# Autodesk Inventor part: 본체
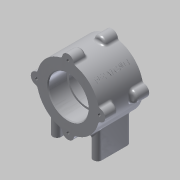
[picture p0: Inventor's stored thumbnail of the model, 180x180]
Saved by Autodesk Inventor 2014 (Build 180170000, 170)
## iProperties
Created: 2015-03
Part Number: 본체
Material: 알루미늄 6061
Document SubType Name: Modeling
Designer: MYHOME
Density: 2.71 g/cm^3
Appearance: 알루미늄 - 평지
Mass: 450.776 g
Surface Area: 332.745 cm^2
Volume: 166.338 cm^3
Author: MYHOME
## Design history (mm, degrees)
sketch "스케치2"
  geometry: C1 r 37 at (0, 0); 1 further point
  constraints: 1 centre point, 1 coincident
  dimensions: "d0" = 74 diameter of C1
extrude "돌출1" new body sketch "스케치2" distance "d1" = 26; taper "d2" = 0 deg
sketch "스케치3"
  geometry: C1 r 7 at (0, 37); C2 r 7 at (-37, 0); C3 r 7 at (37, 0); C4 r 7 at (0, -37); A1 r 37 centre (0, 0) between (0, 37) and (-37, 0) reference
  constraints: 4 centre point, 4 point on circle, 2 horizontal alignment, 2 vertical alignment
  dimensions: "d3" = 7 radius of C1; "d4" = 7 radius of C2; "d5" = 7 radius of C3; "d6" = 7 radius of C4
extrude "돌출2" join sketch "스케치3" distance "d7" = 15; taper "d8" = 0 deg
sketch "스케치4"
  geometry: A1 r 7 centre (37, 0) between (36.338, -6.969) and (36.338, 6.969) reference; A2 r 7 centre (0, 37) between (6.969, 36.338) and (-6.969, 36.338) reference; A3 r 7 centre (-37, 0) between (-36.338, 6.969) and (-36.338, -6.969) reference; A4 r 7 centre (0, -37) between (-6.969, -36.338) and (6.969, -36.338) reference; 4 further points
  constraints: 4 coincident
hole "구멍1" sketch "스케치4" at (0, 37), (-37, 0), (0, -37), (37, 0) diameter "d9" = 3.242; stored, may be unused: countersink angle "d13" = 90 deg, drill point angle "d15" = 118 deg; dims "d10" = 8, "d11" = 4, "d12" = 2, "d14" = 11
fillet "모깎기1" dims "d16" = 3
fillet "모깎기2" dims "d17" = 3
fillet "모깎기3" dims "d18" = 3
hole "구멍2" diameter "d21" = 42; stored, may be unused: countersink angle "d25" = 90 deg, drill point angle "d27" = 0 deg; dims "d19" = 10, "d20" = 10, "d22" = 8, "d23" = 47, "d24" = 22, "d26" = 26
chamfer "모따기1" distance "d28" = 1; stored, may be unused: second distance "d29" = 2, angle "d30" = 45 deg
fillet "모깎기4" dims "d31" = 0.3
node "작업 평면1"
sketch "스케치6"
  geometry: L1 (-24, 15)-(-24, -15); L2 (-29, 15)-(-29, -15); L3 (-19, -15)-(-19, 15); L4 (24, 15)-(24, -15); L5 (29, 15)-(29, -15); L6 (19, -15)-(19, 15); L7 (0, 0)-(0, 20); A1 r 5 centre (-24, 15) between (-19, 15) and (-29, 15); A2 r 5 centre (-24, -15) between (-29, -15) and (-19, -15); A3 r 5 centre (24, 15) between (29, 15) and (19, 15); A4 r 5 centre (24, -15) between (19, -15) and (29, -15); 2 further points
  constraints: 18 end point, 8 point on circle, 8 tangent, 4 centre point, 4 parallel, 2 horizontal alignment, 2 midpoint, 1 symmetric about line, 1 vertical
  dimensions: "d33" = 40 dimension on A3 A4; "d34" = 40 dimension on A1 A2; "d36" = 5 radius of A1; "d37" = 48 distance of L4.end L1.end; "d38" = 10 distance between parallel lines of L5 L6; "d39" = 20 distance of L7.start L7.end
extrude "돌출3" join sketch "스케치6" stored distance "d40" = 15; taper "d41" = 0 deg
sketch "스케치7"
  geometry: L1 (29, 15)-(29, -15) reference; L2 (19, -15)-(19, 15) reference; A1 r 5 centre (-24, -15) between (-29, -15) and (-19, -15) reference; A2 r 5 centre (-24, 15) between (-19, 15) and (-29, 15) reference; A3 r 5 centre (24, 15) between (29, 15) and (19, 15) reference; A4 r 5 centre (24, -15) between (19, -15) and (29, -15) reference; 5 further points
  constraints: 4 coincident
hole "구멍3" sketch "스케치7" at (-24, 15), (-24, -15), (24, -15), (24, 15) diameter "d42" = 4.134; stored, may be unused: countersink angle "d46" = 90 deg, drill point angle "d48" = 118 deg; dims "d43" = 6, "d44" = 47, "d45" = 22, "d47" = 8
fillet "모깎기5" dims "d49" = 3
sketch "스케치8"
  geometry: L1 (0, 0)-(-21, 0); L2 (0, 0)-(-26.163, 26.163); A1 r 37 centre (0, 0) between (-9.104, 35.863) and (-35.863, 9.104) reference; 1 further point
  constraints: 5 end point, 1 horizontal, 1 horizontal alignment, 1 point on circle, 1 other
  dimensions: "d51" = 45 deg angle of L2 L1
node "작업 평면3"
sketch "스케치9"
  geometry: 2 further points
  constraints: 1 coincident, 1 other
feature "엠보싱1" sketch "스케치9" dims "d53" = 0.5, "d54" = 0
node "솔리드1"
mirror "대칭1"
mirror "대칭2"
node "투영된 루프1"
other parameters: "d32" = -56
